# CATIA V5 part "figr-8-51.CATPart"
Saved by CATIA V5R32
Part number: Part1
Bounding box of the stored display mesh (mm): x -75 to 75, y -75 to 75, z 0 to 10
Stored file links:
  D:\PROJECTS\Project 2022\CATIA V5 6R 2022\Resources\Part Files\c08_catia_v5_6r2022_prt\figr-8-51.CATPart
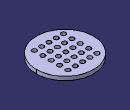
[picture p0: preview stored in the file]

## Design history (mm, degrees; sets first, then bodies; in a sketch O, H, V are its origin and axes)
Body1 (main body)
  Sketch1 on xy-plane, origin (0, 0, 0), H (1, 0, 0), V (0, 1, 0)
    circle A1 centre (0, 0) radius 75
    point P1 (0, 75)
    radius A1 = 75
    coincidence: A1 P1, P1 V
  Pad1: profile Sketch1, direction (0, 0, 1), length 10
  Sketch2 on face of Pad1, origin (0, 0, 10), H (1, 0, 0), V (0, 1, 0)
    circle A1 centre (35, -45) radius 6
    point P1 (35, -45)
    distance P1 H = 45
    distance V P1 = 35
    radius A1 = 6
  Pocket1: profile Sketch2, direction (0, 0, -1), through (limit type 3)
  RectPattern1: of Pocket1, direction 1 instances 5, spacing 19, along xy-plane reversed, direction 2 instances 5, spacing 22, along xy-plane
  Affinity1: ToTransfor RectPattern1, RatioX 1, RatioY 1, RatioZ 1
